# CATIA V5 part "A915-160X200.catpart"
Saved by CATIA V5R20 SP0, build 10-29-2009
Part number: A915-160X200
Source: Unknown
Property "A": "110.000"
Property "ARTICLENO": "A915-160X200"
Property "BOMINFO": "A915-160X200"
Property "CODE": "A915-160X200"
Property "CREATOR": "CADENAS GmbH"
Property "D": "13.500"
Property "D1": "20.000"
Property "FORM": "C"
Property "L": "200.000"
Property "L1": "25.000"
Property "L2": "150.000"
Property "LINA": "A915-160X200"
Property "NB": "A915-160X200"
Property "NBSYN": "$CODE."
Property "NN": "A915"
Property "NT": "VDI 3357 Wear Plates, steel"
Property "SCREW": "M12x25"
Property "SUPPLIER": "CF"
Property "T": "13.000"
Property "W": "160.000"
Bounding box of the stored display mesh (mm): x 0 to 20, y 0 to 200, z -80 to 80
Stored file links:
  C:\Users\borellobunino\Desktop\3D X SITO CF\A915\GSB_OILLESS_G22501160200\CATIAV5\A915-160X200.catpart
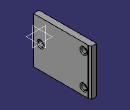
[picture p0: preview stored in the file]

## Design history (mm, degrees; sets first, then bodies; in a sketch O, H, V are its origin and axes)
Body1 "Geometry.1" (main body)
  Solid1 "A915-160X200.catpart": solid without history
